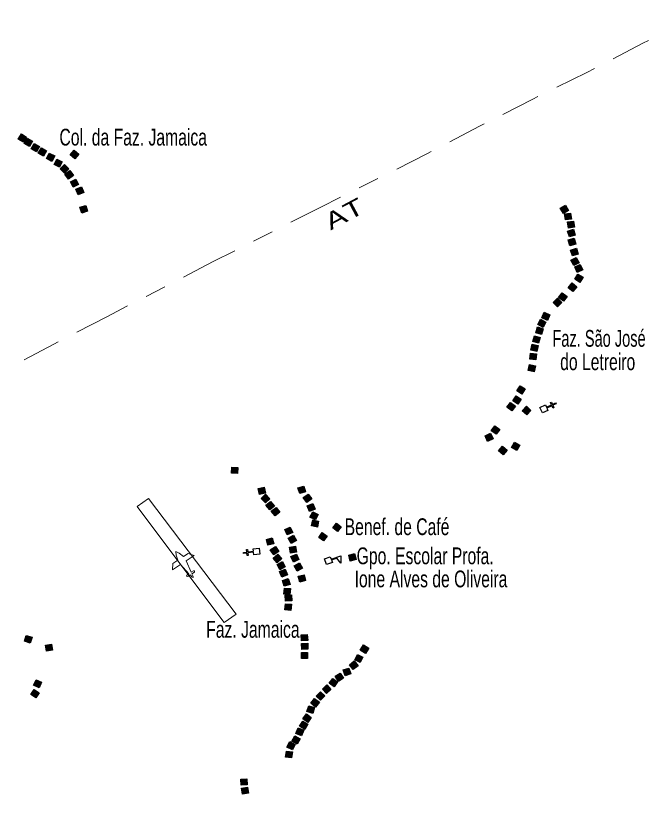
# Model space of a CAD drawing. Extents: x 679 to 705, y 7427.4 to 7455.4.
# Drawn here: x 694.583 to 697.636, y 7439.999 to 7443.755 of the extents above; entities that cross this region are included whole.
import ezdxf
from ezdxf.enums import TextEntityAlignment as Align

# ---------------------------------------------------------------- set-up
doc = ezdxf.new("R2010")
doc.units = 0
doc.header["$LTSCALE"] = 0.032
doc.linetypes.add('DOT_DASHED', pattern=[7.7, 5, -1.2, 0.3, -1.2])
for name, color, linetype, lineweight in [('18', 7, 'Continuous', 13), ('2', 7, 'Continuous', 25), ('4', 7, 'Continuous', 25), ('56', 7, 'DOT_DASHED', 13), ('6', 7, 'Continuous', 25)]:
    doc.layers.add(name, color=color, linetype=linetype, lineweight=lineweight)
doc.layers.add('61', color=7, linetype='Continuous')

msp = doc.modelspace()

# ---------------------------------------------------------------- hatches: boundary and pattern name
at = {"layer": '2'}
for points in [[(694.6094, 7443.1918), (694.6343, 7443.1769), (694.6194, 7443.152), (694.5945, 7443.1669)], [(694.6376, 7443.1709), (694.6629, 7443.1567), (694.6487, 7443.1314), (694.6234, 7443.1456)], [(694.6712, 7443.1454), (694.6964, 7443.131), (694.682, 7443.1058), (694.6568, 7443.1202)], [(694.7047, 7443.1247), (694.7299, 7443.1103), (694.7155, 7443.0851), (694.6903, 7443.0995)], [(694.7683, 7443.0868), (694.7551, 7443.0609), (694.7293, 7443.0741), (694.7425, 7443.1)], [(694.8616, 7443.1142), (694.8834, 7443.0951), (694.8643, 7443.0733), (694.8425, 7443.0924)], [(694.7786, 7443.0717), (694.8046, 7443.0587), (694.7916, 7443.0328), (694.7656, 7443.0458)], [(694.8156, 7443.0457), (694.8355, 7443.0245), (694.8144, 7443.0047), (694.7945, 7443.0258)], [(694.8405, 7443.0167), (694.8574, 7442.9932), (694.8339, 7442.9763), (694.8169, 7442.9998)], [(694.869, 7442.9761), (694.882, 7442.9502), (694.856, 7442.9372), (694.8431, 7442.9632)], [(694.8956, 7442.9391), (694.907, 7442.9124), (694.8804, 7442.901), (694.8689, 7442.9277)], [(694.9164, 7442.8506), (694.9252, 7442.823), (694.8976, 7442.8141), (694.8888, 7442.8417)], [(697.2033, 7442.8521), (697.2182, 7442.8272), (697.1934, 7442.8123), (697.1784, 7442.8372)], [(697.228, 7442.8136), (697.2317, 7442.7849), (697.203, 7442.7812), (697.1993, 7442.8099)], [(697.2425, 7442.7752), (697.246, 7442.7465), (697.2172, 7442.743), (697.2137, 7442.7718)], [(697.2411, 7442.7372), (697.2498, 7442.7096), (697.2221, 7442.7009), (697.2134, 7442.7286)], [(697.2448, 7442.6939), (697.2526, 7442.666), (697.2247, 7442.6582), (697.2169, 7442.6861)], [(697.2555, 7442.6463), (697.2641, 7442.6185), (697.2363, 7442.61), (697.2278, 7442.6377)], [(697.2552, 7442.603), (697.269, 7442.5775), (697.2435, 7442.5637), (697.2297, 7442.5892)], [(697.274, 7442.5691), (697.286, 7442.5427), (697.2596, 7442.5307), (697.2476, 7442.5571)], [(697.2623, 7442.5233), (697.2873, 7442.5085), (697.2726, 7442.4835), (697.2476, 7442.4983)], [(697.2347, 7442.4807), (697.2574, 7442.4626), (697.2392, 7442.44), (697.2166, 7442.4581)], [(697.1882, 7442.4344), (697.2111, 7442.4166), (697.1934, 7442.3937), (697.1704, 7442.4115)], [(697.1864, 7442.3871), (697.1656, 7442.367), (697.1454, 7442.3879), (697.1663, 7442.408)], [(697.1292, 7442.329), (697.1175, 7442.3025), (697.091, 7442.3143), (697.1027, 7442.3408)], [(697.1106, 7442.294), (697.0967, 7442.2686), (697.0713, 7442.2825), (697.0852, 7442.3079)], [(697.098, 7442.2623), (697.0892, 7442.2347), (697.0616, 7442.2435), (697.0704, 7442.2711)], [(697.0835, 7442.2213), (697.0753, 7442.1934), (697.0475, 7442.2016), (697.0556, 7442.2294)], [(697.0735, 7442.182), (697.0665, 7442.1539), (697.0383, 7442.1609), (697.0454, 7442.1891)], [(697.0653, 7442.1431), (697.0629, 7442.1142), (697.034, 7442.1166), (697.0364, 7442.1455)], [(697.0606, 7442.0849), (697.054, 7442.0567), (697.0257, 7442.0633), (697.0324, 7442.0916)], [(696.9868, 7441.9908), (697.0113, 7441.9753), (696.9959, 7441.9508), (696.9713, 7441.9662)], [(696.9678, 7441.9429), (696.9922, 7441.9273), (696.9766, 7441.9029), (696.9522, 7441.9185)], [(696.9422, 7441.9113), (696.9653, 7441.8938), (696.9478, 7441.8707), (696.9247, 7441.8882)], [(697.0177, 7441.8924), (697.0387, 7441.8724), (697.0188, 7441.8514), (696.9977, 7441.8713)], [(696.8668, 7441.7996), (696.8903, 7441.7826), (696.8733, 7441.7591), (696.8498, 7441.7761)], [(696.8464, 7441.7636), (696.8585, 7441.7373), (696.8321, 7441.7252), (696.82, 7441.7515)], [(696.9036, 7441.7025), (696.9255, 7441.6835), (696.9065, 7441.6615), (696.8846, 7441.6805)], [(696.9604, 7441.7209), (696.9856, 7441.7066), (696.9713, 7441.6814), (696.9461, 7441.6957)], [(695.6416, 7441.6004), (695.6398, 7441.5715), (695.6108, 7441.5733), (695.6127, 7441.6023)], [(695.9558, 7441.5121), (695.9643, 7441.4844), (695.9366, 7441.4759), (695.928, 7441.5036)], [(695.7665, 7441.5066), (695.7729, 7441.4783), (695.7446, 7441.472), (695.7382, 7441.5002)], [(695.7741, 7441.4728), (695.7941, 7441.4518), (695.7732, 7441.4318), (695.7531, 7441.4527)], [(695.9765, 7441.4742), (695.9939, 7441.451), (695.9707, 7441.4336), (695.9533, 7441.4568)], [(695.7978, 7441.4392), (695.8163, 7441.4169), (695.794, 7441.3984), (695.7755, 7441.4207)], [(695.8239, 7441.4104), (695.8417, 7441.3876), (695.8189, 7441.3697), (695.801, 7441.3926)], [(695.999, 7441.4282), (696.0097, 7441.4013), (695.9828, 7441.3905), (695.972, 7441.4175)], [(696.0242, 7441.3768), (696.0113, 7441.3509), (695.9853, 7441.3639), (695.9983, 7441.3898)], [(696.0267, 7441.3447), (696.021, 7441.3163), (695.9926, 7441.322), (695.9983, 7441.3504)], [(696.1115, 7441.3353), (696.1346, 7441.3178), (696.117, 7441.2947), (696.0939, 7441.3122)], [(695.8917, 7441.3167), (695.9031, 7441.2901), (695.8765, 7441.2787), (695.865, 7441.3053)], [(696.0443, 7441.2906), (696.0676, 7441.2734), (696.0503, 7441.2501), (696.027, 7441.2673)], [(695.8056, 7441.265), (695.8133, 7441.237), (695.7853, 7441.2294), (695.7777, 7441.2573)], [(695.9071, 7441.2775), (695.9215, 7441.2524), (695.8964, 7441.2379), (695.8819, 7441.2631)], [(695.8205, 7441.224), (695.8366, 7441.1999), (695.8125, 7441.1838), (695.7964, 7441.2079)], [(695.9167, 7441.2251), (695.9211, 7441.1964), (695.8925, 7441.192), (695.8881, 7441.2207)], [(695.8322, 7441.1876), (695.8515, 7441.166), (695.8298, 7441.1466), (695.8105, 7441.1683)], [(695.9211, 7441.188), (695.9327, 7441.1614), (695.9061, 7441.1498), (695.8945, 7441.1764)], [(696.198, 7441.1899), (696.2055, 7441.1619), (696.1774, 7441.1544), (696.17, 7441.1825)], [(695.8543, 7441.1517), (695.8679, 7441.1261), (695.8423, 7441.1125), (695.8287, 7441.1381)], [(695.935, 7441.1455), (695.9495, 7441.1204), (695.9243, 7441.1059), (695.9098, 7441.1311)], [(695.8672, 7441.1161), (695.8783, 7441.0893), (695.8516, 7441.0781), (695.8404, 7441.1049)], [(695.8815, 7441.0707), (695.8902, 7441.043), (695.8626, 7441.0343), (695.8538, 7441.062)], [(695.9575, 7441.0893), (695.9645, 7441.0611), (695.9364, 7441.0541), (695.9293, 7441.0822)], [(695.8921, 7441.0231), (695.8899, 7440.9942), (695.861, 7440.9964), (695.8632, 7441.0253)], [(695.8968, 7440.9929), (695.8982, 7440.9639), (695.8692, 7440.9626), (695.8678, 7440.9915)], [(695.8973, 7440.948), (695.8946, 7440.9192), (695.8658, 7440.9218), (695.8684, 7440.9507)], [(694.6604, 7440.7908), (694.6517, 7440.7631), (694.624, 7440.7717), (694.6327, 7440.7994)], [(695.9725, 7440.8043), (695.9746, 7440.7754), (695.9457, 7440.7733), (695.9436, 7440.8023)], [(694.7532, 7440.7576), (694.758, 7440.729), (694.7294, 7440.7242), (694.7246, 7440.7528)], [(695.9746, 7440.7624), (695.9757, 7440.7334), (695.9467, 7440.7324), (695.9457, 7440.7613)], [(695.9736, 7440.7188), (695.9736, 7440.6898), (695.9446, 7440.6898), (695.9446, 7440.7188)], [(696.2414, 7440.7542), (696.2655, 7440.7381), (696.2494, 7440.714), (696.2253, 7440.7301)], [(696.2115, 7440.7087), (696.2378, 7440.6964), (696.2254, 7440.6701), (696.1992, 7440.6825)], [(696.171, 7440.6442), (696.1801, 7440.6167), (696.1526, 7440.6075), (696.1435, 7440.6351)], [(696.1964, 7440.678), (696.2144, 7440.6552), (696.1916, 7440.6372), (696.1737, 7440.66)], [(696.13, 7440.6202), (696.1453, 7440.5956), (696.1207, 7440.5802), (696.1054, 7440.6048)], [(694.706, 7440.5765), (694.6941, 7440.55), (694.6677, 7440.5619), (694.6795, 7440.5884)], [(696.0938, 7440.5948), (696.1173, 7440.5779), (696.1004, 7440.5543), (696.0768, 7440.5712)], [(694.6941, 7440.5259), (694.6784, 7440.5015), (694.654, 7440.5171), (694.6697, 7440.5415)], [(696.056, 7440.5111), (696.036, 7440.4901), (696.015, 7440.51), (696.0349, 7440.531)], [(696.066, 7440.5632), (696.0854, 7440.5416), (696.0639, 7440.5222), (696.0445, 7440.5438)], [(696.0303, 7440.4811), (696.0125, 7440.4582), (695.9896, 7440.4759), (696.0073, 7440.4989)], [(696.0075, 7440.4556), (695.9986, 7440.428), (695.971, 7440.4368), (695.9798, 7440.4645)], [(695.9919, 7440.4084), (695.975, 7440.3849), (695.9514, 7440.4018), (695.9683, 7440.4253)], [(695.9756, 7440.3765), (695.9607, 7440.3516), (695.9358, 7440.3664), (695.9507, 7440.3914)], [(695.9555, 7440.3472), (695.9444, 7440.3205), (695.9176, 7440.3316), (695.9288, 7440.3584)], [(695.9387, 7440.307), (695.9248, 7440.2816), (695.8994, 7440.2955), (695.9132, 7440.3209)], [(695.9147, 7440.2799), (695.9016, 7440.254), (695.8757, 7440.2671), (695.8888, 7440.293)], [(695.9022, 7440.2439), (695.8979, 7440.2152), (695.8692, 7440.2194), (695.8735, 7440.2481)], [(695.6842, 7440.1159), (695.6859, 7440.087), (695.6569, 7440.0853), (695.6552, 7440.1142)], [(695.6872, 7440.0758), (695.6923, 7440.0473), (695.6637, 7440.0422), (695.6586, 7440.0707)]]:
    msp.add_hatch(color=256, dxfattribs=at).paths.add_polyline_path(points)

# ---------------------------------------------------------------- linework, layer by layer
at = {"layer": '18'}
for points in [[(695.1615, 7441.4152), (695.5745, 7440.8625), (695.5759, 7440.8616), (695.6342, 7440.9016), (695.2157, 7441.4526)], [(695.3466, 7441.2), (695.3616, 7441.1923), (695.3817, 7441.1759), (695.4045, 7441.1908), (695.4338, 7441.1803), (695.3955, 7441.155), (695.4197, 7441.1018), (695.4296, 7441.1085), (695.4353, 7441.1071), (695.4342, 7441.1015), (695.4228, 7441.094), (695.4285, 7441.0807), (695.4283, 7441.0755), (695.4233, 7441.0773), (695.4137, 7441.088), (695.4025, 7441.0805), (695.3967, 7441.0817), (695.3979, 7441.0875), (695.4074, 7441.0939), (695.3685, 7441.1372), (695.3302, 7441.112), (695.3319, 7441.1431), (695.3547, 7441.1581), (695.3476, 7441.1832)]]:
    msp.add_lwpolyline(points, close=True, dxfattribs=at)
at = {"layer": '2'}
for points in [[(694.6094, 7443.1918), (694.6343, 7443.1769), (694.6194, 7443.152), (694.5945, 7443.1669)], [(694.6376, 7443.1709), (694.6629, 7443.1567), (694.6487, 7443.1314), (694.6234, 7443.1456)], [(694.6712, 7443.1454), (694.6964, 7443.131), (694.682, 7443.1058), (694.6568, 7443.1202)], [(694.7047, 7443.1247), (694.7299, 7443.1103), (694.7155, 7443.0851), (694.6903, 7443.0995)], [(694.7683, 7443.0868), (694.7551, 7443.0609), (694.7293, 7443.0741), (694.7425, 7443.1)], [(694.8616, 7443.1142), (694.8834, 7443.0951), (694.8643, 7443.0733), (694.8425, 7443.0924)], [(694.7786, 7443.0717), (694.8046, 7443.0587), (694.7916, 7443.0328), (694.7656, 7443.0458)], [(694.8156, 7443.0457), (694.8355, 7443.0245), (694.8144, 7443.0047), (694.7945, 7443.0258)], [(694.8405, 7443.0167), (694.8574, 7442.9932), (694.8339, 7442.9763), (694.8169, 7442.9998)], [(694.869, 7442.9761), (694.882, 7442.9502), (694.856, 7442.9372), (694.8431, 7442.9632)], [(694.8956, 7442.9391), (694.907, 7442.9124), (694.8804, 7442.901), (694.8689, 7442.9277)], [(694.9164, 7442.8506), (694.9252, 7442.823), (694.8976, 7442.8141), (694.8888, 7442.8417)], [(697.2033, 7442.8521), (697.2182, 7442.8272), (697.1934, 7442.8123), (697.1784, 7442.8372)], [(697.228, 7442.8136), (697.2317, 7442.7849), (697.203, 7442.7812), (697.1993, 7442.8099)], [(697.2425, 7442.7752), (697.246, 7442.7465), (697.2172, 7442.743), (697.2137, 7442.7718)], [(697.2411, 7442.7372), (697.2498, 7442.7096), (697.2221, 7442.7009), (697.2134, 7442.7286)], [(697.2448, 7442.6939), (697.2526, 7442.666), (697.2247, 7442.6582), (697.2169, 7442.6861)], [(697.2555, 7442.6463), (697.2641, 7442.6185), (697.2363, 7442.61), (697.2278, 7442.6377)], [(697.2552, 7442.603), (697.269, 7442.5775), (697.2435, 7442.5637), (697.2297, 7442.5892)], [(697.274, 7442.5691), (697.286, 7442.5427), (697.2596, 7442.5307), (697.2476, 7442.5571)], [(697.2623, 7442.5233), (697.2873, 7442.5085), (697.2726, 7442.4835), (697.2476, 7442.4983)], [(697.2347, 7442.4807), (697.2574, 7442.4626), (697.2392, 7442.44), (697.2166, 7442.4581)], [(697.1882, 7442.4344), (697.2111, 7442.4166), (697.1934, 7442.3937), (697.1704, 7442.4115)], [(697.1864, 7442.3871), (697.1656, 7442.367), (697.1454, 7442.3879), (697.1663, 7442.408)], [(697.1292, 7442.329), (697.1175, 7442.3025), (697.091, 7442.3143), (697.1027, 7442.3408)], [(697.1106, 7442.294), (697.0967, 7442.2686), (697.0713, 7442.2825), (697.0852, 7442.3079)], [(697.098, 7442.2623), (697.0892, 7442.2347), (697.0616, 7442.2435), (697.0704, 7442.2711)], [(697.0835, 7442.2213), (697.0753, 7442.1934), (697.0475, 7442.2016), (697.0556, 7442.2294)], [(697.0735, 7442.182), (697.0665, 7442.1539), (697.0383, 7442.1609), (697.0454, 7442.1891)], [(697.0653, 7442.1431), (697.0629, 7442.1142), (697.034, 7442.1166), (697.0364, 7442.1455)], [(697.0606, 7442.0849), (697.054, 7442.0567), (697.0257, 7442.0633), (697.0324, 7442.0916)], [(696.9868, 7441.9908), (697.0113, 7441.9753), (696.9959, 7441.9508), (696.9713, 7441.9662)], [(696.9678, 7441.9429), (696.9922, 7441.9273), (696.9766, 7441.9029), (696.9522, 7441.9185)], [(696.9422, 7441.9113), (696.9653, 7441.8938), (696.9478, 7441.8707), (696.9247, 7441.8882)], [(697.0177, 7441.8924), (697.0387, 7441.8724), (697.0188, 7441.8514), (696.9977, 7441.8713)], [(696.8668, 7441.7996), (696.8903, 7441.7826), (696.8733, 7441.7591), (696.8498, 7441.7761)], [(696.8464, 7441.7636), (696.8585, 7441.7373), (696.8321, 7441.7252), (696.82, 7441.7515)], [(696.9036, 7441.7025), (696.9255, 7441.6835), (696.9065, 7441.6615), (696.8846, 7441.6805)], [(696.9604, 7441.7209), (696.9856, 7441.7066), (696.9713, 7441.6814), (696.9461, 7441.6957)], [(695.6416, 7441.6004), (695.6398, 7441.5715), (695.6108, 7441.5733), (695.6127, 7441.6023)], [(695.9558, 7441.5121), (695.9643, 7441.4844), (695.9366, 7441.4759), (695.928, 7441.5036)], [(695.7665, 7441.5066), (695.7729, 7441.4783), (695.7446, 7441.472), (695.7382, 7441.5002)], [(695.7741, 7441.4728), (695.7941, 7441.4518), (695.7732, 7441.4318), (695.7531, 7441.4527)], [(695.9765, 7441.4742), (695.9939, 7441.451), (695.9707, 7441.4336), (695.9533, 7441.4568)], [(695.7978, 7441.4392), (695.8163, 7441.4169), (695.794, 7441.3984), (695.7755, 7441.4207)], [(695.8239, 7441.4104), (695.8417, 7441.3876), (695.8189, 7441.3697), (695.801, 7441.3926)], [(695.999, 7441.4282), (696.0097, 7441.4013), (695.9828, 7441.3905), (695.972, 7441.4175)], [(696.0242, 7441.3768), (696.0113, 7441.3509), (695.9853, 7441.3639), (695.9983, 7441.3898)], [(696.0267, 7441.3447), (696.021, 7441.3163), (695.9926, 7441.322), (695.9983, 7441.3504)], [(696.1115, 7441.3353), (696.1346, 7441.3178), (696.117, 7441.2947), (696.0939, 7441.3122)], [(695.8917, 7441.3167), (695.9031, 7441.2901), (695.8765, 7441.2787), (695.865, 7441.3053)], [(696.0443, 7441.2906), (696.0676, 7441.2734), (696.0503, 7441.2501), (696.027, 7441.2673)], [(695.8056, 7441.265), (695.8133, 7441.237), (695.7853, 7441.2294), (695.7777, 7441.2573)], [(695.9071, 7441.2775), (695.9215, 7441.2524), (695.8964, 7441.2379), (695.8819, 7441.2631)], [(695.8205, 7441.224), (695.8366, 7441.1999), (695.8125, 7441.1838), (695.7964, 7441.2079)], [(695.9167, 7441.2251), (695.9211, 7441.1964), (695.8925, 7441.192), (695.8881, 7441.2207)], [(695.8322, 7441.1876), (695.8515, 7441.166), (695.8298, 7441.1466), (695.8105, 7441.1683)], [(695.9211, 7441.188), (695.9327, 7441.1614), (695.9061, 7441.1498), (695.8945, 7441.1764)], [(696.198, 7441.1899), (696.2055, 7441.1619), (696.1774, 7441.1544), (696.17, 7441.1825)], [(695.8543, 7441.1517), (695.8679, 7441.1261), (695.8423, 7441.1125), (695.8287, 7441.1381)], [(695.935, 7441.1455), (695.9495, 7441.1204), (695.9243, 7441.1059), (695.9098, 7441.1311)], [(695.8672, 7441.1161), (695.8783, 7441.0893), (695.8516, 7441.0781), (695.8404, 7441.1049)], [(695.8815, 7441.0707), (695.8902, 7441.043), (695.8626, 7441.0343), (695.8538, 7441.062)], [(695.9575, 7441.0893), (695.9645, 7441.0611), (695.9364, 7441.0541), (695.9293, 7441.0822)], [(695.8921, 7441.0231), (695.8899, 7440.9942), (695.861, 7440.9964), (695.8632, 7441.0253)], [(695.8968, 7440.9929), (695.8982, 7440.9639), (695.8692, 7440.9626), (695.8678, 7440.9915)], [(695.8973, 7440.948), (695.8946, 7440.9192), (695.8658, 7440.9218), (695.8684, 7440.9507)], [(694.6604, 7440.7908), (694.6517, 7440.7631), (694.624, 7440.7717), (694.6327, 7440.7994)], [(695.9725, 7440.8043), (695.9746, 7440.7754), (695.9457, 7440.7733), (695.9436, 7440.8023)], [(694.7532, 7440.7576), (694.758, 7440.729), (694.7294, 7440.7242), (694.7246, 7440.7528)], [(695.9746, 7440.7624), (695.9757, 7440.7334), (695.9467, 7440.7324), (695.9457, 7440.7613)], [(695.9736, 7440.7188), (695.9736, 7440.6898), (695.9446, 7440.6898), (695.9446, 7440.7188)], [(696.2414, 7440.7542), (696.2655, 7440.7381), (696.2494, 7440.714), (696.2253, 7440.7301)], [(696.2115, 7440.7087), (696.2378, 7440.6964), (696.2254, 7440.6701), (696.1992, 7440.6825)], [(696.171, 7440.6442), (696.1801, 7440.6167), (696.1526, 7440.6075), (696.1435, 7440.6351)], [(696.1964, 7440.678), (696.2144, 7440.6552), (696.1916, 7440.6372), (696.1737, 7440.66)], [(696.13, 7440.6202), (696.1453, 7440.5956), (696.1207, 7440.5802), (696.1054, 7440.6048)], [(694.706, 7440.5765), (694.6941, 7440.55), (694.6677, 7440.5619), (694.6795, 7440.5884)], [(696.0938, 7440.5948), (696.1173, 7440.5779), (696.1004, 7440.5543), (696.0768, 7440.5712)], [(694.6941, 7440.5259), (694.6784, 7440.5015), (694.654, 7440.5171), (694.6697, 7440.5415)], [(696.056, 7440.5111), (696.036, 7440.4901), (696.015, 7440.51), (696.0349, 7440.531)], [(696.066, 7440.5632), (696.0854, 7440.5416), (696.0639, 7440.5222), (696.0445, 7440.5438)], [(696.0303, 7440.4811), (696.0125, 7440.4582), (695.9896, 7440.4759), (696.0073, 7440.4989)], [(696.0075, 7440.4556), (695.9986, 7440.428), (695.971, 7440.4368), (695.9798, 7440.4645)], [(695.9919, 7440.4084), (695.975, 7440.3849), (695.9514, 7440.4018), (695.9683, 7440.4253)], [(695.9756, 7440.3765), (695.9607, 7440.3516), (695.9358, 7440.3664), (695.9507, 7440.3914)], [(695.9555, 7440.3472), (695.9444, 7440.3205), (695.9176, 7440.3316), (695.9288, 7440.3584)], [(695.9387, 7440.307), (695.9248, 7440.2816), (695.8994, 7440.2955), (695.9132, 7440.3209)], [(695.9147, 7440.2799), (695.9016, 7440.254), (695.8757, 7440.2671), (695.8888, 7440.293)], [(695.9022, 7440.2439), (695.8979, 7440.2152), (695.8692, 7440.2194), (695.8735, 7440.2481)], [(695.6842, 7440.1159), (695.6859, 7440.087), (695.6569, 7440.0853), (695.6552, 7440.1142)], [(695.6872, 7440.0758), (695.6923, 7440.0473), (695.6637, 7440.0422), (695.6586, 7440.0707)]]:
    msp.add_lwpolyline(points, close=True, dxfattribs=at)
at = {"layer": '4'}
for points in [[(696.0881, 7441.1591), (696.0921, 7441.1477), (696.0648, 7441.138), (696.0551, 7441.1653), (696.0824, 7441.175), (696.0864, 7441.1637)], [(696.0864, 7441.1637), (696.132, 7441.18), (696.1325, 7441.1442), (696.1127, 7441.1679), (696.0881, 7441.1591)]]:
    msp.add_lwpolyline(points, dxfattribs=at)
at = {"layer": '56'}
msp.add_lwpolyline([(697.8309, 7443.7554), (697.5731, 7443.6239), (697.3054, 7443.4844), (697.0473, 7443.3579), (696.7941, 7443.2281), (696.542, 7443.0961), (696.037, 7442.8424), (695.524, 7442.5825), (695.0163, 7442.3198), (694.7641, 7442.1893), (694.5164, 7442.0571), (694.2681, 7441.9019), (693.8232, 7441.5914), (693.7292, 7441.5206), (693.5456, 7441.3652), (693.3793, 7441.1375), (693.1926, 7440.9018), (693.0052, 7440.6906), (692.8076, 7440.4806), (692.6854, 7440.3538), (692.4502, 7440.1946), (692.1694, 7440.0116), (691.9405, 7439.8452)], dxfattribs=at)
at = {"layer": '6'}
for points in [[(697.1147, 7441.8838), (697.1198, 7441.8728), (697.0935, 7441.8607), (697.0813, 7441.887), (697.1076, 7441.8992), (697.1127, 7441.8882)], [(697.1127, 7441.8882), (697.1373, 7441.8995), (697.1323, 7441.9105), (697.1367, 7441.9126), (697.1418, 7441.9016), (697.1567, 7441.9085), (697.1587, 7441.9041), (697.1438, 7441.8972), (697.1488, 7441.8862), (697.1444, 7441.8842), (697.1393, 7441.8952), (697.1147, 7441.8838)], [(695.7168, 7441.1962), (695.6898, 7441.1932), (695.6912, 7441.1812), (695.6863, 7441.1806), (695.685, 7441.1926), (695.6687, 7441.1908), (695.6681, 7441.1956), (695.6844, 7441.1974), (695.6831, 7441.2094), (695.6879, 7441.21), (695.6893, 7441.198), (695.7162, 7441.201)], [(695.7162, 7441.201), (695.7149, 7441.213), (695.7437, 7441.2163), (695.7469, 7441.1875), (695.7181, 7441.1842), (695.7168, 7441.1962)]]:
    msp.add_lwpolyline(points, dxfattribs=at)

# ---------------------------------------------------------------- texts
at = {"layer": '61'}
for s, width, p in [('Col. da Faz. Jamaica', 0.7, (694.791, 7443.1363)), ('Faz. São José', 0.65, (697.1413, 7442.1766)), ('do Letreiro', 0.7, (697.1782, 7442.065)), ('Benef. de Café', 0.7, (696.1508, 7441.2782)), ('Gpo. Escolar Profa.', 0.7, (696.208, 7441.1392)), ('Ione Alves de Oliveira', 0.7, (696.1982, 7441.0292)), ('Faz. Jamaica', 0.7, (695.4906, 7440.7886))]:
    msp.add_text(s, height=0.08, dxfattribs=dict(at, width=width)).set_placement(p)
at = {"layer": '61', "width": 1.4}
msp.add_text('AT', height=0.08, rotation=28.128, dxfattribs=at).set_placement((696.1676, 7442.7753), align=Align.CENTER)

doc.saveas('drawing.dxf')
